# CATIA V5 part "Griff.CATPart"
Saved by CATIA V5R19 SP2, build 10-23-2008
Part number: Griff
Bounding box of the stored display mesh (mm): x -11 to 11, y 0 to 50.652, z -157.527 to 0
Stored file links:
  C:\Catia-Schulung\10 - Catia-Schulung - 13.01.-17.07.2014\09 - Generative_Sheetmetal_Design - Übungen\Kartuschenhalter\Griff.CATPart
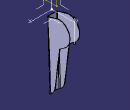
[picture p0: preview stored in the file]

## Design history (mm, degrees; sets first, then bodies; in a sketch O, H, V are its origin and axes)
SheetMetalParameters1: Thickness 0.7, BendRadius 1, KFactor 0.363983 {= log(min(100,max(20*SheetMetalParameters1.BendRadius,SheetMetalParameters1.Thickness)/SheetMetalParameters1.Thickness))/log(100)/2}, ReliefRadialLength 1, ReliefAxialLength 2, MinimumBendRadius 0
AxisSystem1: origin (0, 0, 0), X (1, 0, 0), Y (0, 1, 0), Z (0, 0, 1)
Set1 "Hilfsgeometrie"
  Point1: type Between, FirstPoint vertex [face of Loft1 | face of Loft1 | face of Loft1], SecondPoint vertex [face of Loft1 | face of Loft1 | face of Loft1], Ratio 0.5
  Point2: type Between, FirstPoint vertex [face of Loft1 | face of Loft1 | face of Loft1 | face of Loft1], SecondPoint vertex [face of Loft1 | face of Loft1 | face of Loft1 | face of Loft1], Ratio 0.5
Set2 "Flaechen"
  Loft1: Sections (Sketch2; Sketch1), SectionCouplingPoints ({coupling CouplingPoints (vertex [element of Sketch2 | element of Sketch2]; vertex [element of Sketch1 | element of Sketch1])}; {coupling CouplingPoints (vertex [element of Sketch2 | element of Sketch2]; vertex [element of Sketch1 | element of Sketch1])})
Set3 "Ebenen"
  Plane1: type Offset, RefPlane XY plane of AxisSystem1, Offset 158, reversed
Set4 "Skizzen"
  Sketch1 on Plane1, origin (0, 0, -158), H (1, 0, 0), V (0, 1, 0)
    spline S1 through (-11, 9) (-10, 5) (-6, 1.2) (0, 0) (6, 1.2) (10, 5) (11, 9)
    construction line L1 (-11, 9) -> (-11, 4)
    point P1 (-11, 9)
    point P2 (-11, 4)
    line L2 (-11, 9) -> (-11, 100)
    line L3 (11, 9) -> (11, 100)
    point P4 (11, 9)
    point P6 (-11, 4)
    construction line L4 (-11, 100) -> (11, 100)
    point P7 (0, 0)
    point P8 (-6, 1.2)
    point P9 (6, 1.2)
    point P10 (-11, 9)
    point P11 (11, 9)
    point P12 (-10, 5)
    point P13 (10, 5)
    distance P1 H = 9
    distance P12 H = 5
    distance P12 V = 10
    distance P8 H = 1.2
    distance P8 V = 6
    distance P1 V = 11
    distance H L4 = 100
    coincidence: P7 O, P10 P1, P2 P6, P11 P4, P13 S1
    symmetry: P8 P9 V, P10 P11 V, P12 P13 V, P1 P4 V
    vertical: L1 V, L2 V, L3 V
    horizontal: L4 H
  Sketch2 on XY plane of AxisSystem1, origin (0, 0, 0), H (1, 0, 0), V (0, 1, 0)
    line L1 (-9.5, 0) -> (9.5, 0)
    point P2 (-11, 1.5)
    point P3 (11, 1.5)
    construction line L2 (-11, 1.5) -> (11, 1.5)
    arc A1 centre (-9.5, 1.5) radius 1.5 from (-11, 1.5) to (-9.5, 0) ccw
    point P5 (11, 1.5)
    point P6 (9.5, 1.5)
    arc A2 centre (9.5, 1.5) radius 1.5 from (11, 1.5) to (9.5, 0) cw
    line L3 (-11, 1.5) -> (-11, 100)
    line L4 (11, 1.5) -> (11, 100)
    construction line L5 (-11, 100) -> (11, 100)
    distance P3 P2 = 22
    radius A1 = 1.5
    distance L5 H = 100
    horizontal: L1 H, L2 H, L5 H
    coincidence: L1 H, P6 L2
    symmetry: P2 P3 V, P2 P5 V, A1 A2 V
    tangency: A1 L1, L3 A1, L4 A2
  Sketch3 on face of Loft1, origin (11, 0, 0), H (0, 1, 0), V (0, 0, 1)
    arc A1 centre (-6.4256, -133.0402) radius 25 from (-31.1064, -137.0224) to (18.3806, -136.1477) ccw
    point P1 (-6.4256, -133.0402)
    line L1 (18.3806, -136.1477) -> (28.2433, -57.4157)
    point P3 (28.2433, -57.4157)
    line L2 (28.2433, -57.4157) -> (40.3675, -48.5837)
    point P4 (40.3675, -48.5837)
    arc A2 centre (24.7644, -27.1643) radius 26.5 from (40.3675, -48.5837) to (39.6008, -5.2068) ccw
    point P6 (39.6008, -5.2068)
    arc A3 centre (27.5333, -23.0664) radius 21.5543 from (39.6008, -5.2068) to (21.5875, -2.3483) ccw
    point P8 (21.5875, -2.3483)
    line L3 (21.5875, -2.3483) -> (2.3635, -7.8653)
    point P9 (2.3635, -7.8653)
    construction line L4 (-8.7761, -0.0661) -> (-5.9749, -158.5362)
    point P10 (-8.7761, -0.0661)
    point P11 (-5.9749, -158.5362)
    reference projected point E1 (-5.9749, -158.5362) from Point1
    reference projected point E2 (-8.7761, -0.0661) from Point2
    point P12 (-43.7455, -58.6882)
    line L5 (-31.1064, -137.0224) -> (-43.7455, -58.6882)
    point P13 (-56.1742, -50.2903)
    line L6 (-43.7455, -58.6882) -> (-56.1742, -50.2903)
    point P14 (-56.941, -6.9133)
    arc A4 centre (-41.3379, -28.3327) radius 26.5 from (-56.1742, -50.2903) to (-56.941, -6.9133) cw
    point P16 (-39.04, -3.42)
    arc A5 centre (-44.2499, -24.3353) radius 21.5543 from (-56.941, -6.9133) to (-39.04, -3.42) cw
    point P18 (-19.633, -8.2542)
    line L7 (-39.04, -3.42) -> (-19.633, -8.2542)
    line L8 (-19.633, -8.2542) -> (2.3635, -7.8653)
    construction line L9 (28.2433, -57.4157) -> (-7.7511, -58.0519)
    point P20 (-7.7511, -58.0519)
    construction line L10 (-56.941, -6.9133) -> (-56.1742, -50.2903)
    distance P18 P9 = 22
    distance P11 A1 = 0.5
    distance L8 A1 = 150
    radius A2 = 26.5
    radius A1 = 25
    distance L9 A1 = 100
    distance P3 P4 = 15
    distance P9 P8 = 20
    angle L8 L3 = 15
    radius A3 = 21.5543 (reference)
    distance P12 P3 = 72
    tangency: L1 A1, A2 L2, A3 A2, L3 A3
    coincidence: P11 E1, P10 E2, P1 L4, P20 L4
    symmetry: P3 P12 L4, L1 L5 L4, P4 P13 L4, L2 L6 L4, P6 P14 L4, A2 A4 L4, P8 P16 L4, A3 A5 L4, P9 P18 L4, L3 L7 L4
    perpendicularity: L9 L4
    parallelism: L10 L4
  Sketch4 on face of Loft1, origin (-11, 0, 0), H (0, -1, 0), V (0, 0, 1)
    construction line L1 (8.7761, -0.0661) -> (5.9749, -158.5362)
    point P1 (8.7761, -0.0661)
    point P2 (5.9749, -158.5362)
    reference projected point E1 (8.7761, -0.0661) from Point2
    reference projected point E2 (5.9749, -158.5362) from Point1
    line L2 (-38.2708, -2.2998) -> (-39.1528, -52.2003)
    point P3 (-38.2708, -2.2998)
    reference projected point E3 (-38.7413, -4.7908) from vertex [face of CutOut1 | face of CutOut1 | face of Loft1]
    distance L2 L1 = 47
    coincidence: P1 E1, P2 E2, P3 E3
  Sketch5 on face of Loft1, origin (10.3, 0, 0), H (0, -1, 0), V (0, 0, 1)
    line L1 (50.1205, 3.1825) -> (50.1205, -63.4035)
    vertical: L1 V
Body1 (main body)
Body2 "Griff"
  Hopper1: KFacteur 0.363983 {= SheetMetalParameters1.KFactor}, HopperFixedSideType 0, HopperType 1, Hopper_DeductionTable SheetMetalParameters1, Hopper_InvariantPoint vertex [face of Loft1], Hopper_NeutralFiber 0, Hopper_ReferenceEdge edge of Loft1, Hopper_Surface Loft1, Hopper_Thickness 0.7
  CutOut1: Direction Sketch3, EndLimit through (limit type 2), Orientation true, Profile Sketch3, StartLimit through (limit type 2)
